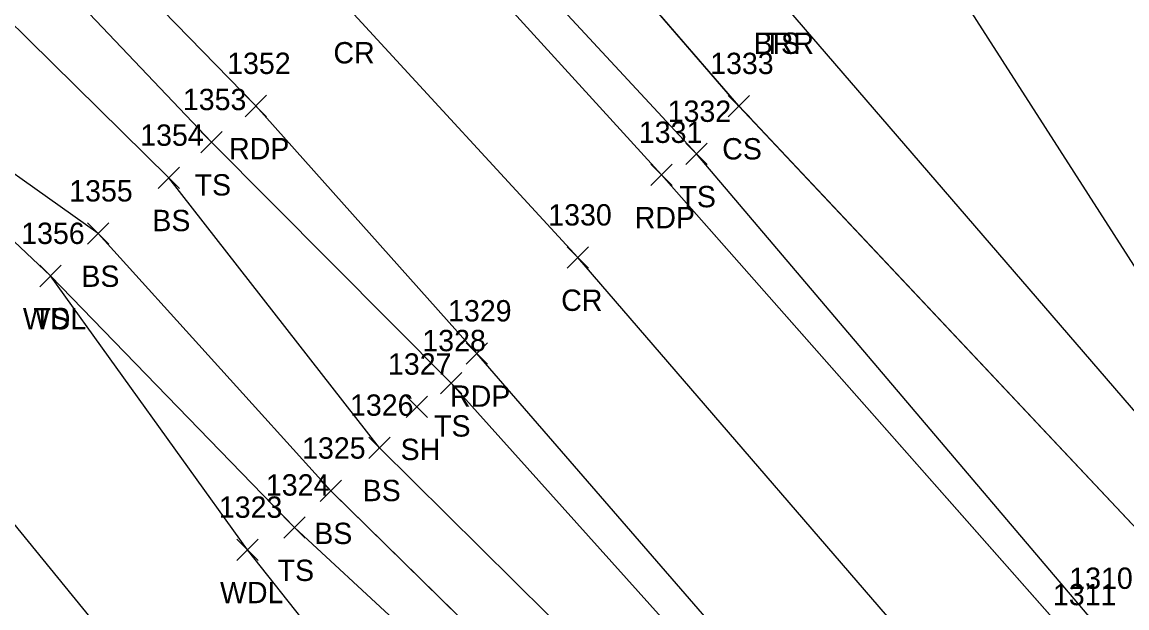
# Model space of a CAD drawing. Extents: x 1415642 to 1422021, y 544543 to 547232.
# Drawn here: x 1416260.5 to 1416364, y 546640.6 to 546695.5 of the extents above; entities that cross this region are included whole.
import ezdxf

# ---------------------------------------------------------------- set-up
doc = ezdxf.new("R2010")
doc.units = 0
for name, color, linetype in [('L_A', 7, 'Continuous'), ('L_I', 7, 'Continuous'), ('L_TIC', 7, 'Continuous'), ('LABL', 7, 'Continuous'), ('LAWA', 7, 'Continuous'), ('LELB', 7, 'Continuous'), ('P_A', 7, 'Continuous'), ('P_I', 7, 'Continuous'), ('P_TIC', 7, 'Continuous'), ('PET', 7, 'Continuous'), ('PRC', 7, 'Continuous')]:
    doc.layers.add(name, color=color, linetype=linetype)

msp = doc.modelspace()

# ---------------------------------------------------------------- linework, layer by layer
at = {"layer": 'L_TIC'}
for points in [[(1416326.63, 546686.63), (1416328.63, 546688.63)], [(1416328.63, 546686.63), (1416326.63, 546688.63)], [(1416277.22, 546683.25), (1416279.22, 546685.25)], [(1416279.22, 546683.25), (1416277.22, 546685.25)], [(1416322.65, 546682.15), (1416324.65, 546684.15)], [(1416324.65, 546682.15), (1416322.65, 546684.15)], [(1416273.22, 546679.91), (1416275.22, 546681.91)], [(1416275.22, 546679.91), (1416273.22, 546681.91)], [(1416266.58, 546674.69), (1416268.58, 546676.69)], [(1416268.58, 546674.69), (1416266.58, 546676.69)], [(1416262.12, 546670.71), (1416264.12, 546672.71)], [(1416264.12, 546670.71), (1416262.12, 546672.71)], [(1416262.12, 546670.71), (1416264.12, 546672.71)], [(1416264.12, 546670.71), (1416262.12, 546672.71)], [(1416299.66, 546660.66), (1416301.66, 546662.66)], [(1416301.66, 546660.66), (1416299.66, 546662.66)], [(1416296.45, 546658.46), (1416298.45, 546660.46)], [(1416298.45, 546658.46), (1416296.45, 546660.46)], [(1416292.94, 546654.61), (1416294.94, 546656.61)], [(1416294.94, 546654.61), (1416292.94, 546656.61)], [(1416288.4, 546650.59), (1416290.4, 546652.59)], [(1416290.4, 546650.59), (1416288.4, 546652.59)], [(1416285, 546647.13), (1416287, 546649.13)], [(1416287, 546647.13), (1416285, 546649.13)], [(1416280.6, 546645.05), (1416282.6, 546647.05)], [(1416282.6, 546645.05), (1416280.6, 546647.05)]]:
    msp.add_lwpolyline(points, dxfattribs=at)
at = {"layer": 'LABL'}
for points in [[(1416444.47, 546650.39), (1416449.12, 546622.32), (1416453.47, 546601.16), (1416449.42, 546597.09), (1416447.84, 546594.51), (1416444.98, 546593.05), (1416441.96, 546593.48), (1416418.31, 546638.92), (1416405.03, 546665.65), (1416399.91, 546654.53), (1416396.19, 546650.28), (1416389.66, 546643.26), (1416382.8, 546639.59), (1416370.88, 546651.88), (1416331.53, 546697.52), (1416315.15, 546719.28), (1416313.42, 546715.93), (1416308.55, 546724.26), (1416301.62, 546736.74), (1416278.11, 546774.25)], [(1416444.47, 546650.39), (1416449.12, 546622.32), (1416453.47, 546601.16), (1416449.42, 546597.08), (1416447.84, 546594.51), (1416444.98, 546593.04), (1416441.96, 546593.48), (1416418.31, 546638.92), (1416405.03, 546665.65), (1416399.91, 546654.53), (1416396.19, 546650.28), (1416389.66, 546643.27), (1416382.81, 546639.59), (1416370.88, 546651.88), (1416331.54, 546697.52), (1416315.15, 546719.28), (1416313.42, 546715.93), (1416308.55, 546724.26), (1416301.62, 546736.74), (1416278.12, 546774.25)]]:
    msp.add_lwpolyline(points, dxfattribs=at)
at = {"layer": 'LAWA'}
for points in [[(1416366.86, 546544.85), (1416337.81, 546578.41), (1416315.28, 546603.5), (1416281.6, 546646.05), (1416263.12, 546671.71), (1416234.79, 546698.48), (1416216.66, 546718.21), (1416189.47, 546748.09), (1416170.48, 546756.81)], [(1416366.86, 546544.85), (1416337.81, 546578.41), (1416315.28, 546603.5), (1416281.6, 546646.05), (1416263.12, 546671.71), (1416234.8, 546698.48), (1416216.66, 546718.21), (1416189.46, 546748.09), (1416170.49, 546756.81)]]:
    msp.add_lwpolyline(points, dxfattribs=at)
at = {"layer": 'LELB'}
for points in [[(1416413.88, 546519.84), (1416385.73, 546558.12), (1416356.85, 546595.36), (1416336.82, 546621.39), (1416300.66, 546661.66), (1416278.22, 546684.25), (1416249.88, 546714.04), (1416230.93, 546728.9), (1416221.86, 546737.5), (1416200.69, 546756.25), (1416176.24, 546778.44), (1416157.26, 546793.38), (1416140.02, 546808.9), (1416121.84, 546825.58), (1416090.2, 546848.7), (1416061.67, 546872.28), (1416021.03, 546902.96), (1415979.27, 546932.57), (1415964.6, 546940.59)], [(1416413.88, 546519.84), (1416385.73, 546558.12), (1416356.85, 546595.36), (1416336.82, 546621.39), (1416300.66, 546661.66), (1416278.22, 546684.25), (1416249.88, 546714.04), (1416230.93, 546728.9), (1416221.87, 546737.51), (1416200.69, 546756.25), (1416176.24, 546778.44), (1416157.26, 546793.38), (1416140.03, 546808.9), (1416121.84, 546825.58), (1416090.21, 546848.7), (1416061.68, 546872.28), (1416021.04, 546902.96), (1415979.28, 546932.57), (1415964.61, 546940.59)], [(1416487.57, 546505.93), (1416480.71, 546505.12), (1416469.86, 546502.72), (1416462.76, 546510.55), (1416442.83, 546541.19), (1416430.44, 546560.72), (1416424.35, 546585.18), (1416398.34, 546624.28), (1416389.66, 546643.26), (1416377.3, 546653.03), (1416344.54, 546704.05), (1416343.42, 546724.77), (1416329.35, 546768.04), (1416303.68, 546799.52), (1416274.8, 546819.39), (1416239.26, 546839.41), (1416210.61, 546845.46), (1416203.47, 546849.21), (1416195, 546854.49)], [(1416487.57, 546505.93), (1416480.71, 546505.12), (1416469.86, 546502.72), (1416462.76, 546510.55), (1416442.83, 546541.19), (1416430.44, 546560.72), (1416424.35, 546585.18), (1416398.34, 546624.28), (1416389.66, 546643.27), (1416377.3, 546653.03), (1416344.54, 546704.05), (1416343.42, 546724.76), (1416329.35, 546768.04), (1416303.68, 546799.52), (1416274.8, 546819.4), (1416239.26, 546839.41), (1416210.61, 546845.46), (1416203.48, 546849.21), (1416195, 546854.49)], [(1416462.64, 546496.11), (1416437.87, 546538.89), (1416411.19, 546576.82), (1416382.17, 546614.17), (1416360.8, 546639.39), (1416323.65, 546683.15), (1416301.53, 546707.03), (1416273.6, 546735.69), (1416258.67, 546751.22), (1416224.41, 546784.74), (1416201.13, 546806.07), (1416169.09, 546832.26)], [(1416462.64, 546496.11), (1416437.87, 546538.89), (1416411.18, 546576.82), (1416382.17, 546614.17), (1416360.8, 546639.39), (1416323.65, 546683.15), (1416301.53, 546707.03), (1416273.6, 546735.69), (1416258.67, 546751.22), (1416224.4, 546784.74), (1416201.13, 546806.07), (1416169.09, 546832.26)], [(1416578, 546177.77), (1416578.55, 546199.27), (1416573.9, 546214.14), (1416552.43, 546269), (1416536.22, 546304.5), (1416520.22, 546335.71), (1416500.65, 546371.21), (1416484.25, 546405.14), (1416455.06, 546455.78), (1416435.93, 546486.65), (1416412.14, 546519.01), (1416383.64, 546557.13), (1416352.74, 546592.54), (1416331.82, 546618.14), (1416293.94, 546655.61), (1416274.22, 546680.91), (1416245.72, 546708.98), (1416224.27, 546729.93), (1416198.14, 546753.3), (1416170.94, 546765.48), (1416158.5, 546767.31), (1416141.08, 546772.75), (1416136.01, 546776.95), (1416129, 546780.64)], [(1416578, 546177.77), (1416578.55, 546199.27), (1416573.9, 546214.14), (1416552.42, 546269.01), (1416536.22, 546304.5), (1416520.22, 546335.71), (1416500.65, 546371.22), (1416484.25, 546405.15), (1416455.06, 546455.79), (1416435.93, 546486.65), (1416412.14, 546519.01), (1416383.65, 546557.13), (1416352.74, 546592.54), (1416331.82, 546618.14), (1416293.94, 546655.62), (1416274.22, 546680.91), (1416245.72, 546708.98), (1416224.27, 546729.93), (1416198.14, 546753.3), (1416170.94, 546765.48), (1416158.51, 546767.31), (1416141.09, 546772.75), (1416136.01, 546776.96), (1416129.01, 546780.64)], [(1416503.76, 546247.98), (1416498.74, 546274.69), (1416501.23, 546308.66), (1416502.98, 546324.04), (1416489.47, 546365.32), (1416480.57, 546403.46), (1416453.11, 546455.02), (1416433.2, 546484.78), (1416409.26, 546516.78), (1416378.25, 546552.92), (1416343.61, 546583.91), (1416327.57, 546614.09), (1416289.4, 546651.59), (1416267.58, 546675.69), (1416237.14, 546697.31), (1416220.66, 546725.9), (1416195.41, 546750.9), (1416170.78, 546763.33), (1416158.82, 546764.49), (1416140.16, 546770.72), (1416135.4, 546775.05), (1416128.27, 546778.63)], [(1416503.76, 546247.98), (1416498.74, 546274.69), (1416501.24, 546308.65), (1416502.98, 546324.03), (1416489.47, 546365.32), (1416480.57, 546403.46), (1416453.11, 546455.02), (1416433.2, 546484.78), (1416409.26, 546516.79), (1416378.25, 546552.92), (1416343.61, 546583.91), (1416327.58, 546614.09), (1416289.4, 546651.59), (1416267.58, 546675.69), (1416237.14, 546697.31), (1416220.66, 546725.9), (1416195.42, 546750.9), (1416170.78, 546763.33), (1416158.81, 546764.5), (1416140.16, 546770.72), (1416135.4, 546775.05), (1416128.28, 546778.62)], [(1416315.28, 546603.5), (1416270.97, 546634.69), (1416249.08, 546661.51), (1416225.2, 546690.33), (1416216.66, 546718.21)], [(1416315.28, 546603.5), (1416270.97, 546634.69), (1416249.08, 546661.51), (1416225.21, 546690.34), (1416216.66, 546718.21)], [(1416430.44, 546560.72), (1416417.31, 546581.34), (1416388.22, 546619.27), (1416367.45, 546645.31), (1416327.63, 546687.63), (1416307.15, 546711.36)], [(1416430.44, 546560.72), (1416417.31, 546581.35), (1416388.22, 546619.27), (1416367.44, 546645.31), (1416327.63, 546687.64), (1416307.15, 546711.36)], [(1416480.57, 546403.46), (1416449.3, 546452.17), (1416431.01, 546483.64), (1416405.55, 546512.84), (1416372.51, 546548.53), (1416341.49, 546581.99), (1416324.84, 546612.16), (1416286, 546648.13), (1416263.12, 546671.71)], [(1416480.57, 546403.46), (1416449.3, 546452.17), (1416431.01, 546483.64), (1416405.56, 546512.84), (1416372.51, 546548.53), (1416341.49, 546581.99), (1416324.84, 546612.16), (1416286, 546648.13), (1416263.12, 546671.71)]]:
    msp.add_lwpolyline(points, dxfattribs=at)
at = {"layer": 'P_TIC'}
for points in [[(1416281.37, 546686.64), (1416283.37, 546688.64)], [(1416283.37, 546686.64), (1416281.37, 546688.64)], [(1416319.38, 546680.18), (1416321.38, 546682.18)], [(1416321.38, 546680.18), (1416319.38, 546682.18)], [(1416311.55, 546672.44), (1416313.55, 546674.44)], [(1416313.55, 546672.44), (1416311.55, 546674.44)], [(1416302.08, 546663.45), (1416304.08, 546665.45)], [(1416304.08, 546663.45), (1416302.08, 546665.45)]]:
    msp.add_lwpolyline(points, dxfattribs=at)
at = {"layer": 'PET'}
for points in [[(1416435.56, 546537.44), (1416408.53, 546574.61), (1416379.54, 546611.97), (1416358.62, 546637.86), (1416320.38, 546681.18), (1416299.04, 546704.62), (1416270.68, 546734.26), (1416256.1, 546749.21), (1416221.42, 546781.44), (1416197.8, 546803.68), (1416167.45, 546829.93), (1416146.9, 546847.39), (1416116.66, 546870.72), (1416088.42, 546892.72), (1416062.97, 546911.59), (1416031.6, 546935.61), (1415998.08, 546959.73), (1415969.06, 546981.93), (1415936.64, 547006.92)], [(1416435.56, 546537.44), (1416408.53, 546574.62), (1416379.54, 546611.97), (1416358.63, 546637.85), (1416320.38, 546681.18), (1416299.04, 546704.62), (1416270.69, 546734.26), (1416256.1, 546749.21), (1416221.42, 546781.44), (1416197.8, 546803.68), (1416167.45, 546829.93), (1416146.9, 546847.38), (1416116.66, 546870.72), (1416088.42, 546892.72), (1416062.98, 546911.58), (1416031.6, 546935.61), (1415998.08, 546959.73), (1415969.07, 546981.93), (1415936.65, 547006.92)], [(1416417.68, 546520.98), (1416388.9, 546560.28), (1416359.4, 546597.75), (1416339.06, 546622.92), (1416303.08, 546664.45), (1416282.37, 546687.64), (1416253.58, 546717.16), (1416237.44, 546733.28), (1416206.51, 546762.17), (1416181.86, 546784.67), (1416151.94, 546810.47), (1416130.39, 546828.26), (1416101.49, 546851.34), (1416072.78, 546874.03), (1416047.41, 546892.82), (1416017.81, 546915.59), (1415982.21, 546942.39), (1415954.4, 546964.56)], [(1416417.68, 546520.98), (1416388.9, 546560.28), (1416359.4, 546597.76), (1416339.06, 546622.93), (1416303.08, 546664.45), (1416282.37, 546687.65), (1416253.58, 546717.16), (1416237.44, 546733.28), (1416206.51, 546762.17), (1416181.87, 546784.67), (1416151.94, 546810.47), (1416130.39, 546828.26), (1416101.49, 546851.34), (1416072.78, 546874.03), (1416047.41, 546892.82), (1416017.81, 546915.59), (1415982.21, 546942.39), (1415954.4, 546964.56)]]:
    msp.add_lwpolyline(points, dxfattribs=at)
at = {"layer": 'PRC'}
for points in [[(1416425.29, 546532.23), (1416399.16, 546568.17), (1416370.34, 546605), (1416349.98, 546630.03), (1416312.55, 546673.44), (1416291.21, 546696.63), (1416262.58, 546725.99), (1416246.66, 546742.06), (1416214.68, 546772.43), (1416190.4, 546794.67), (1416160.38, 546819.82), (1416139.01, 546837.64), (1416109.6, 546860.71), (1416080.51, 546883.13), (1416051.44, 546902.01), (1416024.84, 546926.07), (1415989.92, 546951.67), (1415962.46, 546973.18)], [(1416425.29, 546532.24), (1416399.16, 546568.17), (1416370.35, 546605), (1416349.98, 546630.03), (1416312.55, 546673.45), (1416291.21, 546696.63), (1416262.58, 546725.99), (1416246.66, 546742.06), (1416214.67, 546772.43), (1416190.4, 546794.67), (1416160.38, 546819.82), (1416139.01, 546837.64), (1416109.6, 546860.71), (1416080.51, 546883.13), (1416051.45, 546902.01), (1416024.84, 546926.07), (1415989.92, 546951.68), (1415962.46, 546973.18)]]:
    msp.add_lwpolyline(points, dxfattribs=at)

# ---------------------------------------------------------------- texts
at = {"layer": 'L_A'}
for s, p in [('BRR', (1416329.02, 546692.52)), ('TS', (1416329.94, 546692.52)), ('CS', (1416326.07, 546682.63)), ('TS', (1416276.63, 546679.25)), ('TS', (1416322.06, 546678.15)), ('BS', (1416272.67, 546675.91)), ('BS', (1416266.02, 546670.69)), ('WDL', (1416260.54, 546666.71)), ('TS', (1416261.53, 546666.71)), ('TS', (1416299.07, 546656.66)), ('SH', (1416295.93, 546654.46)), ('BS', (1416292.38, 546650.61)), ('BS', (1416287.84, 546646.59)), ('TS', (1416284.41, 546643.13)), ('WDL', (1416279.01, 546641.05))]:
    msp.add_text(s, height=2, dxfattribs=at).set_placement(p)
at = {"layer": 'L_I'}
for s, p in [('1333', (1416324.94, 546690.63)), ('1353', (1416275.53, 546687.25)), ('1332', (1416320.96, 546686.15)), ('1354', (1416271.53, 546683.91)), ('1355', (1416264.88, 546678.69)), ('1356', (1416260.38, 546674.71)), ('1356', (1416260.38, 546674.71)), ('1328', (1416297.97, 546664.66)), ('1327', (1416294.75, 546662.46)), ('1326', (1416291.19, 546658.61)), ('1325', (1416286.7, 546654.59)), ('1324', (1416283.31, 546651.13)), ('1323', (1416278.9, 546649.05)), ('1310', (1416358.59, 546642.39))]:
    msp.add_text(s, height=2, dxfattribs=at).set_placement(p)
at = {"layer": 'P_A'}
for s, p in [('CR', (1416289.64, 546691.63)), ('RDP', (1416279.86, 546682.64)), ('RDP', (1416317.87, 546676.18)), ('CR', (1416310.98, 546668.44)), ('RDP', (1416300.57, 546659.45))]:
    msp.add_text(s, height=2, dxfattribs=at).set_placement(p)
at = {"layer": 'P_I'}
for s, p in [('1352', (1416279.68, 546690.64)), ('1331', (1416318.26, 546684.18)), ('1330', (1416309.77, 546676.44)), ('1329', (1416300.38, 546667.45)), ('1311', (1416357.06, 546640.86))]:
    msp.add_text(s, height=2, dxfattribs=at).set_placement(p)

doc.saveas('drawing.dxf')
